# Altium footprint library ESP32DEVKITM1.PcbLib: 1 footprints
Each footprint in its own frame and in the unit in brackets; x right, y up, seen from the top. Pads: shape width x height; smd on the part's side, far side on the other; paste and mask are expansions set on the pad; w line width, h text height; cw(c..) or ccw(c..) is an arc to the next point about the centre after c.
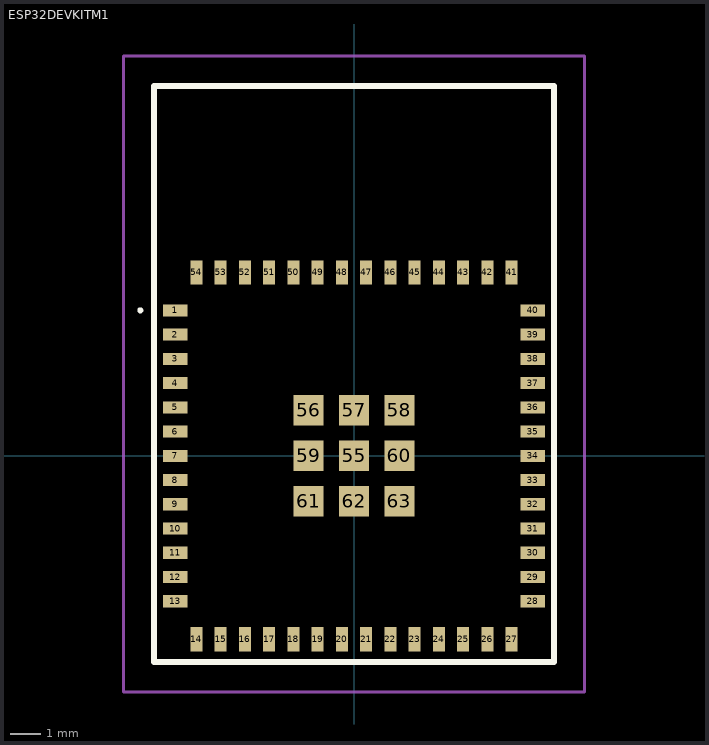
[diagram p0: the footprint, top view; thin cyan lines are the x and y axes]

## ESP32DEVKITM1 [mm]
pads (63):
  rect 0.8x0.4 smd: 1(-5.9,4.8) 2(-5.9,4) 3(-5.9,3.2) 4(-5.9,2.4) 5(-5.9,1.6) 6(-5.9,0.8) 7(-5.9,0) 8(-5.9,-0.8) 9(-5.9,-1.6) 10(-5.9,-2.4) 11(-5.9,-3.2) 12(-5.9,-4) 13(-5.9,-4.8) 28(5.9,-4.8) 29(5.9,-4) 30(5.9,-3.2) 31(5.9,-2.4) 32(5.9,-1.6) 33(5.9,-0.8) 34(5.9,0) 35(5.9,0.8) 36(5.9,1.6) 37(5.9,2.4) 38(5.9,3.2) 39(5.9,4) 40(5.9,4.8)
  rect 0.4x0.8 smd: 14(-5.2,-6.05) 15(-4.4,-6.05) 16(-3.6,-6.05) 17(-2.8,-6.05) 18(-2,-6.05) 19(-1.2,-6.05) 20(-0.4,-6.05) 21(0.4,-6.05) 22(1.2,-6.05) 23(2,-6.05) 24(2.8,-6.05) 25(3.6,-6.05) 26(4.4,-6.05) 27(5.2,-6.05) 41(5.2,6.05) 42(4.4,6.05) 43(3.6,6.05) 44(2.8,6.05) 45(2,6.05) 46(1.2,6.05) 47(0.4,6.05) 48(-0.4,6.05) 49(-1.2,6.05) 50(-2,6.05) 51(-2.8,6.05) 52(-3.6,6.05) 53(-4.4,6.05) 54(-5.2,6.05)
  rect 1x1 smd: 55(0,0) 56(-1.5,1.5) 57(0,1.5) 58(1.5,1.5) 59(-1.5,0) 60(1.5,0) 61(-1.5,-1.5) 62(0,-1.5) 63(1.5,-1.5)
Top Overlay:
  lines w0.1: -7.1,4.8 cw(c-7.05,4.8) -7,4.8 ; -7.1,4.8 -7.1,4.8 ; -7.1,4.8 ccw(c-7.05,4.8) -7,4.8 ; -7,4.8 -7,4.8
  lines w0.2: -6.6,-6.8 6.6,-6.8 6.6,12.2 -6.6,12.2 -6.6,-6.8
Mechanical 15:
  lines w0.1: -6.6,-6.8 6.6,-6.8 6.6,12.2 -6.6,12.2 -6.6,-6.8
Mechanical 20:
  lines w0.1: -7.6,-7.8 7.6,-7.8 7.6,13.2 -7.6,13.2 -7.6,-7.8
